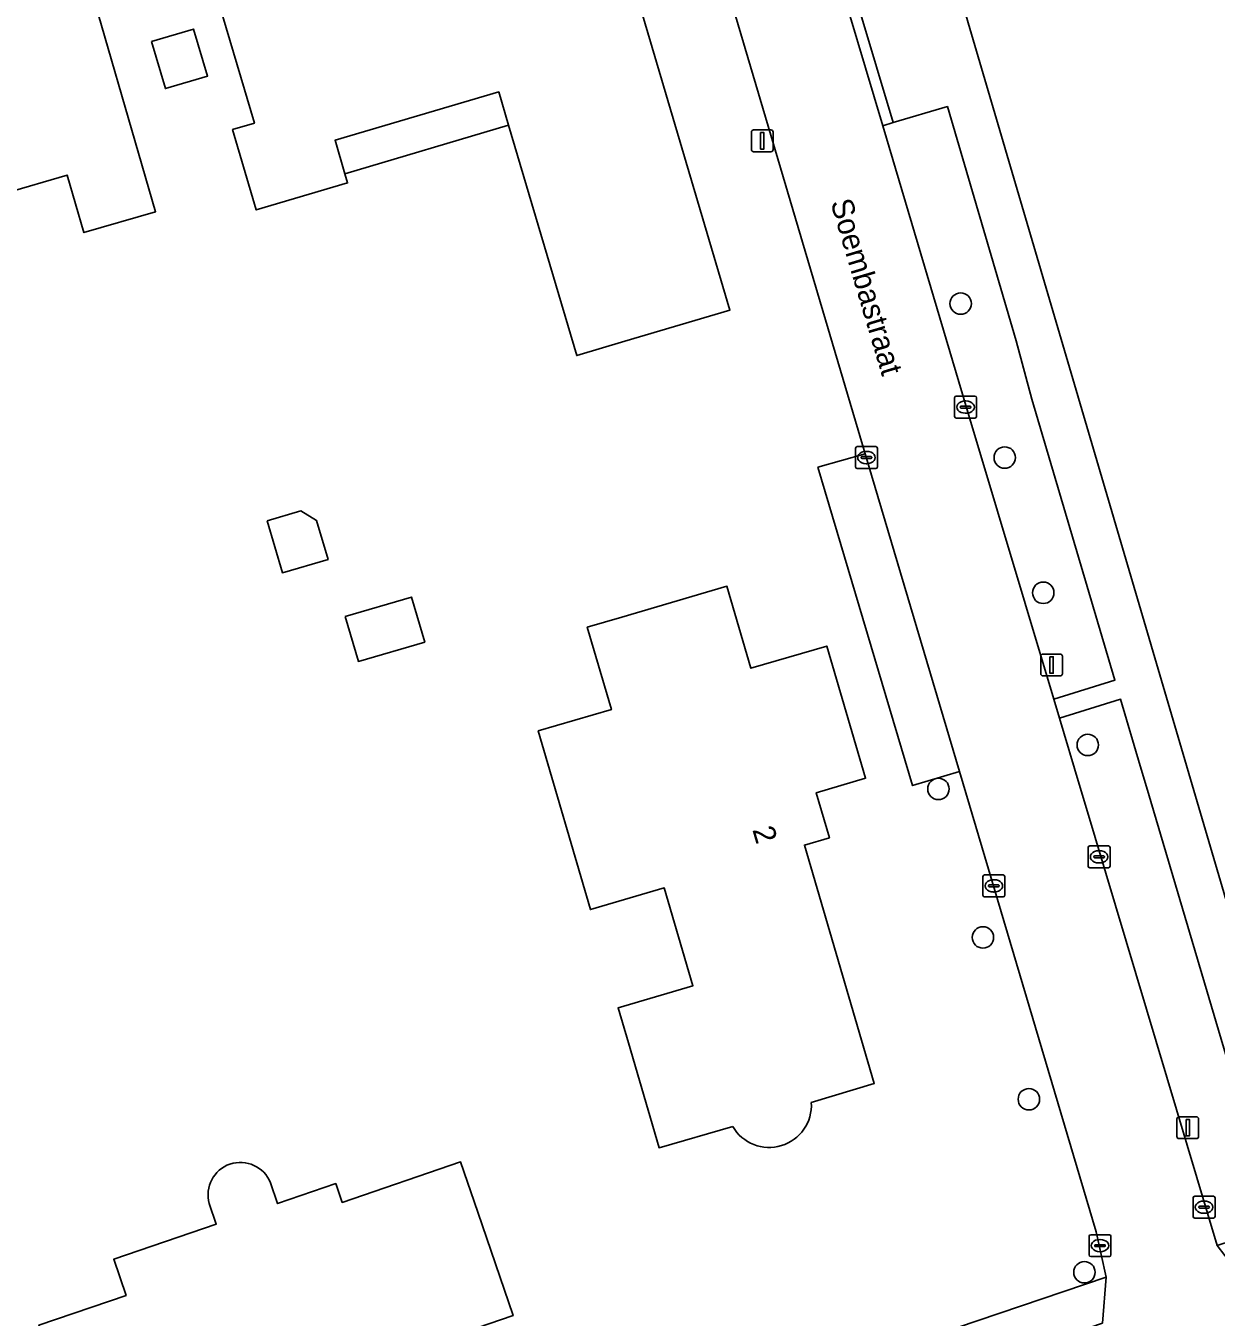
# Model space of a CAD drawing. Extents: x 162417 to 163722, y 384268 to 385417.
# Drawn here: x 163274.6 to 163329, y 384597 to 384656 of the extents above; entities that cross this region are included whole.
import ezdxf

# ---------------------------------------------------------------- set-up
doc = ezdxf.new("R2010")
doc.units = 0
for name, color, linetype in [('IMGEO_Berm_groen', 7, 'Continuous'), ('IMGEO_Boom', 7, 'Continuous'), ('IMGEO_Erf', 7, 'Continuous'), ('IMGEO_Kolk', 7, 'Continuous'), ('IMGEO_Lichtmast', 7, 'Continuous'), ('IMGEO_Openbare_ruimte_label', 7, 'Continuous'), ('IMGEO_Pand', 7, 'Continuous'), ('IMGEO_Pand_nummerreeks', 7, 'Continuous'), ('IMGEO_Pand_overbouw', 7, 'Continuous'), ('IMGEO_Rijbaan_lokaal_open', 7, 'Continuous'), ('IMGEO_Voetpad_open', 7, 'Continuous')]:
    doc.layers.add(name, color=color, linetype=linetype)

msp = doc.modelspace()

# ---------------------------------------------------------------- linework, layer by layer
at = {"layer": 'IMGEO_Berm_groen'}
for points in [[(163316.675, 384652.273), (163314.204, 384651.541), (163313.725, 384651.399), (163317.662, 384638.152), (163321.537, 384625.199), (163324.332, 384626.062), (163320.535, 384638.911), (163319.815, 384641.564)], [(163325.769, 384621.2), (163325.485, 384622.16), (163324.587, 384625.199), (163321.795, 384624.338), (163322.7, 384621.313), (163322.986, 384620.355), (163329.005, 384600.235), (163331.704, 384601.119)]]:
    msp.add_lwpolyline(points, close=True, dxfattribs=at)
at = {"layer": 'IMGEO_Boom'}
for centre in [(163317.284, 384643.273), (163319.297, 384636.239), (163321.054, 384630.059), (163323.09, 384623.109), (163316.269, 384621.1), (163318.299, 384614.313), (163320.398, 384606.923), (163322.938, 384599.019)]:
    msp.add_circle(centre, 0.489, dxfattribs=at)
at = {"layer": 'IMGEO_Erf'}
for points in [[(163310.09, 384681.76), (163333.508, 384602.071), (163340.928, 384604.472), (163346.471, 384606.34), (163371.048, 384614.758), (163375.186, 384616.159), (163389.679, 384621.017), (163394.532, 384622.596), (163398.708, 384624.299), (163402.801, 384626.194), (163403.314, 384626.415), (163406.716, 384627.995)], [(163310.764, 384635.802), (163312.926, 384636.415), (163300.634, 384677.935), (163300.352, 384678.47), (163299.946, 384679.602), (163217.164, 384655.09), (163211.589, 384653.439), (163162.154, 384638.801), (163163.733, 384633.465), (163163.883, 384632.961), (163162.442, 384632.589), (163160.726, 384632.111), (163162.281, 384626.769), (163162.11, 384626.271), (163182.33, 384558.292), (163182.739, 384554.615), (163182.929, 384552.906)], [(163272.155, 384581.269), (163276.448, 384582.722), (163295.04, 384589.014), (163299.601, 384590.557), (163323.936, 384598.792), (163323.475, 384600.863), (163317.237, 384621.888), (163315.089, 384621.253), (163310.764, 384635.802)], [(163306.872, 384605.673), (163303.509, 384604.704), (163302.104, 384609.503), (163301.635, 384611.105), (163305.054, 384612.106), (163303.745, 384616.578), (163300.372, 384615.59), (163297.984, 384623.747), (163301.329, 384624.726), (163300.227, 384628.489), (163301.811, 384628.953), (163306.609, 384630.357), (163307.704, 384626.614), (163311.169, 384627.628), (163312.938, 384621.584), (163310.686, 384620.926), (163311.289, 384618.866), (163310.149, 384618.533), (163313.338, 384607.635), (163310.459, 384606.772)], [(163285.753, 384603.107), (163286.077, 384602.159), (163288.74, 384603.068), (163289.033, 384602.211), (163294.44, 384604.058), (163295.222, 384601.77), (163296.839, 384597.038), (163291.46, 384595.2)], [(163275.182, 384596.604), (163279.16, 384597.963), (163278.596, 384599.612), (163283.282, 384601.213), (163282.96, 384602.156)]]:
    msp.add_lwpolyline(points, dxfattribs=at)
for points in [[(163288.704, 384650.731), (163289.155, 384649.207), (163289.279, 384648.786), (163285.109, 384647.551), (163284.023, 384651.221), (163285.022, 384651.517), (163282.318, 384660.655), (163280.899, 384665.449), (163287.845, 384667.428), (163288.469, 384665.32), (163289.195, 384662.869), (163293.012, 384663.999), (163292.855, 384664.526), (163299.758, 384666.57), (163306.744, 384642.968), (163301.95, 384641.549), (163299.749, 384640.897), (163296.634, 384651.421), (163296.183, 384652.945)], [(163260.25, 384660.667), (163257.838, 384659.974), (163257.742, 384660.3), (163260.157, 384660.994), (163268.278, 384663.328), (163267.585, 384665.72), (163267.913, 384665.805), (163268.6, 384663.42), (163270.078, 384658.288), (163274.054, 384659.406), (163274.19, 384658.922), (163276.954, 384659.724), (163280.51, 384647.464), (163277.235, 384646.514), (163276.473, 384649.14), (163270.819, 384647.5), (163270.801, 384647.562), (163264.63, 384645.772), (163264.607, 384645.854), (163264.482, 384645.818)], [(163280.322, 384655.244), (163282.247, 384655.814), (163282.882, 384653.667), (163280.957, 384653.097)], [(163285.605, 384633.351), (163287.148, 384633.802), (163287.861, 384633.367), (163288.384, 384631.583), (163286.301, 384630.973)], [(163289.17, 384628.974), (163292.199, 384629.861), (163292.8, 384627.809), (163289.77, 384626.922)]]:
    msp.add_lwpolyline(points, close=True, dxfattribs=at)
for centre, radius, start, end in [((163308.535, 384606.648), 1.928, 210.38958, 3.67889), ((163284.381, 384602.56), 1.477, 21.75073, 195.85608)]:
    msp.add_arc(centre, radius, start, end, dxfattribs=at)
at = {"layer": 'IMGEO_Kolk'}
for p, q in [((163317.007, 384638.117), (163317.007, 384638.969)), ((163317.082, 384639.043), (163317.934, 384639.043)), ((163317.495, 384638.823), (163317.52, 384638.823)), ((163318.008, 384638.969), (163318.008, 384638.117)), ((163317.934, 384638.043), (163317.082, 384638.043)), ((163317.266, 384638.537), (163317.266, 384638.549)), ((163317.704, 384638.5), (163317.306, 384638.5)), ((163317.309, 384638.586), (163317.707, 384638.586)), ((163317.518, 384638.263), (163317.493, 384638.263)), ((163317.75, 384638.549), (163317.75, 384638.537)), ((163312.48, 384635.812), (163312.48, 384636.664)), ((163312.555, 384636.738), (163313.407, 384636.738)), ((163312.739, 384636.232), (163312.739, 384636.244)), ((163312.782, 384636.281), (163313.18, 384636.281)), ((163312.968, 384636.518), (163312.993, 384636.518)), ((163313.223, 384636.244), (163313.223, 384636.232)), ((163313.481, 384636.664), (163313.481, 384635.812)), ((163313.407, 384635.738), (163312.555, 384635.738)), ((163313.177, 384636.195), (163312.779, 384636.195)), ((163312.991, 384635.958), (163312.966, 384635.958)), ((163323.107, 384617.572), (163323.107, 384618.424)), ((163323.182, 384618.498), (163324.034, 384618.498)), ((163323.366, 384617.992), (163323.366, 384618.004)), ((163323.804, 384617.955), (163323.406, 384617.955)), ((163323.409, 384618.041), (163323.807, 384618.041)), ((163323.595, 384618.278), (163323.62, 384618.278)), ((163323.85, 384618.004), (163323.85, 384617.992)), ((163324.108, 384618.424), (163324.108, 384617.572)), ((163324.034, 384617.498), (163323.182, 384617.498)), ((163323.618, 384617.718), (163323.593, 384617.718)), ((163318.298, 384616.244), (163318.298, 384617.096)), ((163318.373, 384617.17), (163319.225, 384617.17)), ((163318.786, 384616.95), (163318.811, 384616.95)), ((163319.299, 384617.096), (163319.299, 384616.244)), ((163318.557, 384616.664), (163318.557, 384616.676)), ((163318.995, 384616.627), (163318.597, 384616.627)), ((163318.6, 384616.713), (163318.998, 384616.713)), ((163318.809, 384616.39), (163318.784, 384616.39)), ((163319.041, 384616.676), (163319.041, 384616.664)), ((163319.225, 384616.17), (163318.373, 384616.17)), ((163327.902, 384601.566), (163327.902, 384602.418)), ((163327.977, 384602.492), (163328.829, 384602.492)), ((163328.204, 384602.035), (163328.602, 384602.035)), ((163328.39, 384602.272), (163328.415, 384602.272)), ((163328.903, 384602.418), (163328.903, 384601.566)), ((163328.829, 384601.492), (163327.977, 384601.492)), ((163328.161, 384601.986), (163328.161, 384601.998)), ((163328.599, 384601.949), (163328.201, 384601.949)), ((163328.413, 384601.712), (163328.388, 384601.712)), ((163328.645, 384601.998), (163328.645, 384601.986)), ((163323.148, 384599.809), (163323.148, 384600.661)), ((163323.223, 384600.735), (163324.075, 384600.735)), ((163323.45, 384600.278), (163323.848, 384600.278)), ((163323.636, 384600.515), (163323.661, 384600.515)), ((163324.149, 384600.661), (163324.149, 384599.809)), ((163324.075, 384599.735), (163323.223, 384599.735)), ((163323.407, 384600.229), (163323.407, 384600.241)), ((163323.845, 384600.192), (163323.447, 384600.192)), ((163323.659, 384599.955), (163323.634, 384599.955)), ((163323.891, 384600.241), (163323.891, 384600.229))]:
    msp.add_line(p, q, dxfattribs=at)
for points in [[(163317.007, 384638.117), (163317.007, 384638.969)], [(163317.082, 384639.043), (163317.934, 384639.043)], [(163318.008, 384638.969), (163318.008, 384638.117)], [(163317.934, 384638.043), (163317.082, 384638.043)], [(163312.48, 384635.812), (163312.48, 384636.664)], [(163312.555, 384636.738), (163313.407, 384636.738)], [(163313.481, 384636.664), (163313.481, 384635.812)], [(163313.407, 384635.738), (163312.555, 384635.738)], [(163323.107, 384617.572), (163323.107, 384618.424)], [(163323.182, 384618.498), (163324.034, 384618.498)], [(163324.108, 384618.424), (163324.108, 384617.572)], [(163324.034, 384617.498), (163323.182, 384617.498)], [(163318.298, 384616.244), (163318.298, 384617.096)], [(163318.373, 384617.17), (163319.225, 384617.17)], [(163319.299, 384617.096), (163319.299, 384616.244)], [(163319.225, 384616.17), (163318.373, 384616.17)], [(163327.902, 384601.566), (163327.902, 384602.418)], [(163327.977, 384602.492), (163328.829, 384602.492)], [(163328.903, 384602.418), (163328.903, 384601.566)], [(163328.829, 384601.492), (163327.977, 384601.492)], [(163323.148, 384599.809), (163323.148, 384600.661)], [(163323.223, 384600.735), (163324.075, 384600.735)], [(163324.149, 384600.661), (163324.149, 384599.809)], [(163324.075, 384599.735), (163323.223, 384599.735)]]:
    msp.add_lwpolyline(points, dxfattribs=at)
for centre, radius, start, end in [((163317.084, 384638.967), 0.0765, 91.55205, 178.44795), ((163317.084, 384638.967), 0.0765, 91.55205, 178.44795), ((163317.932, 384638.967), 0.0765, 1.55205, 88.44795), ((163317.932, 384638.967), 0.0765, 1.55205, 88.44795), ((163317.084, 384638.119), 0.0765, 181.55205, 268.44795), ((163317.084, 384638.119), 0.0765, 181.55205, 268.44795), ((163317.306, 384638.546), 0.0403, 85.87752, 175.75265), ((163317.303, 384638.536), 0.0366, 178.93798, 274.71019), ((163317.707, 384638.543), 0.043, 264.86636, 352.45326), ((163317.711, 384638.548), 0.0386, 1.73085, 96.63898), ((163317.932, 384638.119), 0.0765, 271.55205, 358.44795), ((163317.932, 384638.119), 0.0765, 271.55205, 358.44795), ((163312.557, 384636.662), 0.0765, 91.55205, 178.44795), ((163312.557, 384636.662), 0.0765, 91.55205, 178.44795), ((163312.779, 384636.241), 0.0403, 85.87752, 175.75265), ((163313.184, 384636.243), 0.0386, 1.73085, 96.63898), ((163313.405, 384636.662), 0.0765, 1.55205, 88.44795), ((163313.405, 384636.662), 0.0765, 1.55205, 88.44795), ((163312.557, 384635.814), 0.0765, 181.55205, 268.44795), ((163312.557, 384635.814), 0.0765, 181.55205, 268.44795), ((163312.776, 384636.231), 0.0366, 178.93798, 274.71019), ((163313.18, 384636.238), 0.043, 264.86636, 352.45326), ((163313.405, 384635.814), 0.0765, 271.55205, 358.44795), ((163313.405, 384635.814), 0.0765, 271.55205, 358.44795), ((163323.184, 384618.422), 0.0765, 91.55205, 178.44795), ((163323.184, 384618.422), 0.0765, 91.55205, 178.44795), ((163323.406, 384618.001), 0.0403, 85.87752, 175.75265), ((163323.403, 384617.991), 0.0366, 178.93798, 274.71019), ((163323.807, 384617.998), 0.043, 264.86636, 352.45326), ((163323.811, 384618.003), 0.0386, 1.73085, 96.63898), ((163324.032, 384618.422), 0.0765, 1.55205, 88.44795), ((163324.032, 384618.422), 0.0765, 1.55205, 88.44795), ((163323.184, 384617.574), 0.0765, 181.55205, 268.44795), ((163323.184, 384617.574), 0.0765, 181.55205, 268.44795), ((163324.032, 384617.574), 0.0765, 271.55205, 358.44795), ((163324.032, 384617.574), 0.0765, 271.55205, 358.44795), ((163318.375, 384617.094), 0.0765, 91.55205, 178.44795), ((163318.375, 384617.094), 0.0765, 91.55205, 178.44795), ((163319.223, 384617.094), 0.0765, 1.55205, 88.44795), ((163319.223, 384617.094), 0.0765, 1.55205, 88.44795), ((163318.375, 384616.246), 0.0765, 181.55205, 268.44795), ((163318.375, 384616.246), 0.0765, 181.55205, 268.44795), ((163318.597, 384616.673), 0.0403, 85.87752, 175.75265), ((163318.594, 384616.663), 0.0366, 178.93798, 274.71019), ((163318.998, 384616.67), 0.043, 264.86636, 352.45326), ((163319.002, 384616.675), 0.0386, 1.73085, 96.63898), ((163319.223, 384616.246), 0.0765, 271.55205, 358.44795), ((163319.223, 384616.246), 0.0765, 271.55205, 358.44795), ((163327.979, 384602.416), 0.0765, 91.55205, 178.44795), ((163327.979, 384602.416), 0.0765, 91.55205, 178.44795), ((163328.201, 384601.995), 0.0403, 85.87752, 175.75265), ((163328.606, 384601.997), 0.0386, 1.73085, 96.63898), ((163328.827, 384602.416), 0.0765, 1.55205, 88.44795), ((163328.827, 384602.416), 0.0765, 1.55205, 88.44795), ((163327.979, 384601.568), 0.0765, 181.55205, 268.44795), ((163327.979, 384601.568), 0.0765, 181.55205, 268.44795), ((163328.198, 384601.985), 0.0366, 178.93798, 274.71019), ((163328.602, 384601.992), 0.043, 264.86636, 352.45326), ((163328.827, 384601.568), 0.0765, 271.55205, 358.44795), ((163328.827, 384601.568), 0.0765, 271.55205, 358.44795), ((163323.225, 384600.659), 0.0765, 91.55205, 178.44795), ((163323.225, 384600.659), 0.0765, 91.55205, 178.44795), ((163323.447, 384600.238), 0.0403, 85.87752, 175.75265), ((163323.852, 384600.24), 0.0386, 1.73085, 96.63898), ((163324.073, 384600.659), 0.0765, 1.55205, 88.44795), ((163324.073, 384600.659), 0.0765, 1.55205, 88.44795), ((163323.225, 384599.811), 0.0765, 181.55205, 268.44795), ((163323.225, 384599.811), 0.0765, 181.55205, 268.44795), ((163323.444, 384600.228), 0.0366, 178.93798, 274.71019), ((163323.848, 384600.235), 0.043, 264.86636, 352.45326), ((163324.073, 384599.811), 0.0765, 271.55205, 358.44795), ((163324.073, 384599.811), 0.0765, 271.55205, 358.44795)]:
    msp.add_arc(centre, radius, start, end, dxfattribs=at)
for centre, major_axis, ratio, start_param, end_param in [((163317.494, 384638.543), (-0.387, 0.002), 0.722429, 4.712389, 7.853982), ((163317.519, 384638.543), (-0.39, 0.002), 0.717154, 1.570796, 4.712389), ((163312.967, 384636.238), (-0.387, 0.002), 0.722429, 4.712389, 7.853982), ((163312.992, 384636.238), (-0.39, 0.002), 0.717154, 1.570796, 4.712389), ((163323.594, 384617.998), (-0.387, 0.002), 0.722429, 4.712389, 7.853982), ((163323.619, 384617.998), (-0.39, 0.002), 0.717154, 1.570796, 4.712389), ((163318.785, 384616.67), (-0.387, 0.002), 0.722429, 4.712389, 7.853982), ((163318.81, 384616.67), (-0.39, 0.002), 0.717154, 1.570796, 4.712389), ((163328.389, 384601.992), (-0.387, 0.002), 0.722429, 4.712389, 7.853982), ((163328.414, 384601.992), (-0.39, 0.002), 0.717154, 1.570796, 4.712389), ((163323.635, 384600.235), (-0.387, 0.002), 0.722429, 4.712389, 7.853982), ((163323.66, 384600.235), (-0.39, 0.002), 0.717154, 1.570796, 4.712389)]:
    msp.add_ellipse(centre, major_axis=major_axis, ratio=ratio, start_param=start_param, end_param=end_param, dxfattribs=at)
at = {"layer": 'IMGEO_Lichtmast'}
for p, q in [((163307.723, 384650.307), (163307.723, 384651.107)), ((163307.723, 384651.107), (163307.723, 384650.307)), ((163307.823, 384651.207), (163308.613, 384651.207)), ((163308.613, 384651.207), (163307.823, 384651.207)), ((163308.713, 384651.107), (163308.713, 384650.307)), ((163308.713, 384650.307), (163308.713, 384651.107)), ((163308.613, 384650.207), (163307.823, 384650.207)), ((163307.823, 384650.207), (163308.613, 384650.207)), ((163320.942, 384626.362), (163320.942, 384627.162)), ((163320.942, 384627.162), (163320.942, 384626.362)), ((163321.042, 384627.262), (163321.832, 384627.262)), ((163321.832, 384627.262), (163321.042, 384627.262)), ((163321.932, 384627.162), (163321.932, 384626.362)), ((163321.932, 384626.362), (163321.932, 384627.162)), ((163321.832, 384626.262), (163321.042, 384626.262)), ((163321.042, 384626.262), (163321.832, 384626.262)), ((163327.16, 384605.222), (163327.16, 384606.022)), ((163327.16, 384606.022), (163327.16, 384605.222)), ((163327.26, 384606.122), (163328.05, 384606.122)), ((163328.05, 384606.122), (163327.26, 384606.122)), ((163328.15, 384606.022), (163328.15, 384605.222)), ((163328.15, 384605.222), (163328.15, 384606.022)), ((163328.05, 384605.122), (163327.26, 384605.122)), ((163327.26, 384605.122), (163328.05, 384605.122))]:
    msp.add_line(p, q, dxfattribs=at)
for points in [[(163308.143, 384651.082), (163308.293, 384651.082), (163308.293, 384650.332), (163308.143, 384650.332), (163308.143, 384651.082)], [(163321.362, 384627.137), (163321.512, 384627.137), (163321.512, 384626.387), (163321.362, 384626.387), (163321.362, 384627.137)], [(163327.58, 384605.997), (163327.73, 384605.997), (163327.73, 384605.247), (163327.58, 384605.247), (163327.58, 384605.997)]]:
    msp.add_lwpolyline(points, dxfattribs=at)
for centre, start, end in [((163307.823, 384651.107), 90, 180), ((163307.823, 384651.107), 90, 180), ((163308.613, 384651.107), 0, 90), ((163308.613, 384651.107), 360, 90), ((163307.823, 384650.307), 180, 270), ((163307.823, 384650.307), 180, 270), ((163308.613, 384650.307), 270, 0), ((163308.613, 384650.307), 270, 0), ((163321.042, 384627.162), 90, 180), ((163321.042, 384627.162), 90, 180), ((163321.832, 384627.162), 0, 90), ((163321.832, 384627.162), 360, 90), ((163321.042, 384626.362), 180, 270), ((163321.042, 384626.362), 180, 270), ((163321.832, 384626.362), 270, 0), ((163321.832, 384626.362), 270, 0), ((163327.26, 384606.022), 90, 180), ((163327.26, 384606.022), 90, 180), ((163328.05, 384606.022), 0, 90), ((163328.05, 384606.022), 360, 90), ((163327.26, 384605.222), 180, 270), ((163327.26, 384605.222), 180, 270), ((163328.05, 384605.222), 270, 0), ((163328.05, 384605.222), 270, 0)]:
    msp.add_arc(centre, 0.1, start, end, dxfattribs=at)
at = {"layer": 'IMGEO_Pand'}
for points in [[(163288.704, 384650.731), (163296.183, 384652.945), (163296.634, 384651.421), (163299.749, 384640.897), (163301.95, 384641.549), (163306.744, 384642.968), (163299.758, 384666.57), (163292.855, 384664.526), (163293.012, 384663.999), (163289.195, 384662.869), (163288.469, 384665.32), (163287.845, 384667.428), (163280.899, 384665.449), (163282.318, 384660.655), (163285.022, 384651.517), (163284.023, 384651.221), (163285.109, 384647.551), (163289.279, 384648.786), (163289.155, 384649.207)], [(163276.954, 384659.724), (163274.19, 384658.922), (163274.054, 384659.406), (163270.078, 384658.288), (163268.6, 384663.42), (163268.278, 384663.328), (163260.157, 384660.994), (163260.25, 384660.667), (163264.482, 384645.818), (163264.607, 384645.854), (163264.63, 384645.772), (163270.801, 384647.562), (163270.819, 384647.5), (163276.473, 384649.14), (163277.235, 384646.514), (163280.51, 384647.464)], [(163280.322, 384655.244), (163280.957, 384653.097), (163282.882, 384653.667), (163282.247, 384655.814)], [(163285.605, 384633.351), (163286.301, 384630.973), (163288.384, 384631.583), (163287.861, 384633.367), (163287.148, 384633.802)], [(163289.17, 384628.974), (163289.77, 384626.922), (163292.8, 384627.809), (163292.199, 384629.861)]]:
    msp.add_lwpolyline(points, close=True, dxfattribs=at)
for points in [[(163310.459, 384606.772), (163313.338, 384607.635), (163310.149, 384618.533), (163311.289, 384618.866), (163310.686, 384620.926), (163312.938, 384621.584), (163311.169, 384627.628), (163307.704, 384626.614), (163306.609, 384630.357), (163301.811, 384628.953), (163300.227, 384628.489), (163301.329, 384624.726), (163297.984, 384623.747), (163300.372, 384615.59), (163303.745, 384616.578), (163305.054, 384612.106), (163301.635, 384611.105), (163302.104, 384609.503), (163303.509, 384604.704), (163306.872, 384605.673)], [(163282.96, 384602.156), (163283.282, 384601.213), (163278.596, 384599.612), (163279.16, 384597.963), (163275.182, 384596.604), (163275.408, 384595.943), (163277.025, 384591.211), (163281.032, 384592.58), (163281.611, 384590.885), (163286.632, 384592.601), (163286.939, 384592.699), (163288.413, 384593.203), (163288.681, 384593.289), (163291.754, 384594.339), (163291.46, 384595.2), (163296.839, 384597.038), (163295.222, 384601.77), (163294.44, 384604.058), (163289.033, 384602.211), (163288.74, 384603.068), (163286.077, 384602.159), (163285.753, 384603.107)]]:
    msp.add_lwpolyline(points, dxfattribs=at)
for centre, radius, start, end in [((163308.535, 384606.648), 1.928, 210.38958, 3.67889), ((163284.381, 384602.56), 1.477, 21.75073, 195.85608)]:
    msp.add_arc(centre, radius, start, end, dxfattribs=at)
at = {"layer": 'IMGEO_Pand_overbouw'}
msp.add_lwpolyline([(163296.634, 384651.421), (163296.183, 384652.945), (163288.704, 384650.731), (163289.155, 384649.207)], close=True, dxfattribs=at)
at = {"layer": 'IMGEO_Rijbaan_lokaal_open'}
for points in [[(163322.986, 384620.355), (163322.7, 384621.313), (163321.795, 384624.338), (163321.537, 384625.199), (163317.662, 384638.152), (163313.725, 384651.399), (163311.404, 384659.211), (163306.588, 384675.415), (163305.445, 384679.26), (163305.248, 384679.964), (163300.352, 384678.47), (163300.634, 384677.935), (163312.926, 384636.415), (163317.237, 384621.888), (163323.475, 384600.863), (163323.936, 384598.792), (163323.763, 384596.699)], [(163330.054, 384598.864), (163329.005, 384600.235), (163322.986, 384620.355)]]:
    msp.add_lwpolyline(points, dxfattribs=at)
at = {"layer": 'IMGEO_Voetpad_open'}
for points in [[(163310.09, 384681.76), (163309.903, 384682.414), (163307.99, 384681.867), (163308.098, 384681.397), (163309.634, 384676.252), (163310.423, 384673.599), (163314.36, 384660.087), (163311.865, 384659.348), (163314.204, 384651.541), (163316.675, 384652.273), (163319.815, 384641.564), (163320.535, 384638.911), (163324.332, 384626.062), (163321.537, 384625.199), (163321.795, 384624.338), (163324.587, 384625.199), (163325.485, 384622.16), (163325.769, 384621.2), (163331.704, 384601.119), (163333.508, 384602.071)], [(163314.204, 384651.541), (163311.865, 384659.348), (163311.404, 384659.211), (163313.725, 384651.399)], [(163310.764, 384635.802), (163315.089, 384621.253), (163317.237, 384621.888), (163312.926, 384636.415)], [(163323.763, 384596.699), (163323.936, 384598.792), (163299.601, 384590.557), (163300.28, 384588.65)]]:
    msp.add_lwpolyline(points, close=True, dxfattribs=at)

# ---------------------------------------------------------------- texts
at = {"layer": 'IMGEO_Openbare_ruimte_label'}
msp.add_text('Soembastraat', height=1, rotation=286.55114, dxfattribs=at).set_placement((163311.329, 384647.895))
at = {"layer": 'IMGEO_Pand_nummerreeks'}
msp.add_text('2', height=1, rotation=286.31573, dxfattribs=at).set_placement((163307.762, 384619.24))

doc.saveas('drawing.dxf')
